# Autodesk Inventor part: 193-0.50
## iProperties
Created: 2007-06
Part Number: 193-0.50
Document SubType Name: Modeling
Designer: btaylor
Density: 1 g/cm^3
Author: btaylor
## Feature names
1. Sweep1
2. Extrusion1
3. Extrusion2
4. Fillet1
5. Fillet2
6. Extrusion3
7. Extrusion4
8. Chamfer1
9. Chamfer2
10. Fillet3
11. Fillet4
12. Sweep2
13. Fillet5
14. Fillet6
